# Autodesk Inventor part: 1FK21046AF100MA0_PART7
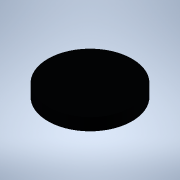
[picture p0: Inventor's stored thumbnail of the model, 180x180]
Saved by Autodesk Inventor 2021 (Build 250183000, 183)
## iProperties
Created: 2025-04
Part Number: 1FK21046AF100MA0_PART7
Material: Generic
Catalog Web Link: www.3dfindit.com
Description: -Servo synchronous motor
Document SubType Name: Modeling
Designer: psAdmin
Mass: 0.299142 g
Surface Area: 3.8585 cm^2
Volume: 0.299142 cm^3
Density: 1 g/cm^3
Appearance: PSOLRGB-38-46-56
Category: PARTsolutions
Title: 1FK21046AF100MA0_PART7
Author: Cadenas PARTsolutions
Comments: Servo synchronous motor
Sending System: PARTsolutions
Preprocessor: ST-DEVELOPER v19.3
PSOL_IDENT_0: {$CADENAS_DATA/23d-libs/siemens_ag/_cat_/4f/2b/1fk21046af100ma0.prj},213 {VTYP=3D},{NB=1FK21046AF100
PSOL_IDENT_1: MA0_PART7},{LINA=1FK21046AF100MA0_PART7},{NN=1FK21046AF100MA0_PART7},{NOPRJ=TRUE},{DATE=19.08.2025 1
PSOL_IDENT_2: 4:00:37},{GEOMDATE=30.07.2025 02:01:06},{VERSION=},{LINEID=10},{WBVAR=},{WBNUMERIC=}  {NB=1FK21046AF
PSOL_IDENT_3: 100MA0_PART7},{LINA=1FK21046AF100MA0_PART7},{KT=DUMMY},{PREVIEW=../../../_pool_/cb/72/p_d211_xx_0043
PSOL_IDENT_4: 4j.png},{DESCSHORT=SIMOTICS S-1FK2 HD, SINAMICS S210 3AC 400V-480V, 3.2 Nm, 3000 rpm},{DESCLONG=SIMO
PSOL_IDENT_5: TICS S-1FK2 HD servo motor M0=3.2 Nm; PN = 1 kW at nN=3000 rpm (380-480 V); PN = 0.5 kW at nN=1500 r
PSOL_IDENT_6: pm (200-240 V); with holding brake; degree of protection IP64; cylindrical shaft D19x40mm; absolute
PSOL_IDENT_7: encoder 22-bit + 12-bit multiturn (encoder AM22DQC); with OCC interface; plug size M17, rotatable; S
PSOL_IDENT_8: IMOTICS S-1FK2 servomotorfor a wide range of uses in industrial environments. SIMOTICS S‑1FK2 servom
PSOL_IDENT_9: otors are compact synchronous motors with a high dynamic performance that set themselves apart as a
PSOL_IDENT_10: result of their high power density, degree of protection and overload capability. The motors are ava
PSOL_IDENT_11: ilable in two variants: as High Dynamic variant (highest dynamic performance as a result of the low
PSOL_IDENT_12: intrinsic moment of inertia for applications demanding a high dynamic performance with low moved mas
PSOL_IDENT_13: ses) - and as Compact variant (precise and stable closed-loop control for medium up to large moved m
PSOL_IDENT_14: asses as a result of a medium intrinsic moment of inertia). SIMOTICSS‑1FK2 servomotors fully exploit
PSOL_IDENT_15: their strengths in a system with the SINAMICSS210 frequency converter and simple connection using t
PSOL_IDENT_16: he one cable connection (OCC). Advantages include the short control and positioning times, fast and
PSOL_IDENT_17: precise correction of disturbing quantities as well as stable control with a high dynamic performanc
PSOL_IDENT_18: e. The servo motors can be configured to address a wide range of requirements. For example with and
PSOL_IDENT_19: without holding brake, IP64 or IP65 degree of protection, singleturn or multiturn absolute encoders
PSOL_IDENT_20: - to name just a few. Further, the servomotors are available in different shaft heights extending fr
PSOL_IDENT_21: om 20 to 100. A shaft sealing ring is available to achieve an IP65 degree of protection and for subs
PSOL_IDENT_22: equent mounting at the motor or as spare part. SIMOTICS - the optimum motor for each and every motio
PSOL_IDENT_23: n control application.},{INTNO=195125049673},{SUPPLIERALTNO=1FK2104-6AF10-0MA0},{MANUID=1FK21046AF10
PSOL_IDENT_24: 0MA0},{MANUNAME=Siemens},{MANUTYPEDESC=Synchronous motor 1FK2-HD 3.2 NM},{AAU732=SIMOTICS},{AAO057=S
PSOL_IDENT_25: -1FK2},{AAU734=SIMOTICS S-1FK2 HD servo motor M0=3.2 Nm; PN = 1 kW at nN=3000 rpm (380-480 V); PN =
PSOL_IDENT_26: 0.5 kW at nN=1500 rpm (200-240 V); with holding brake; degree of protection IP64; cylindrical shaft
PSOL_IDENT_27: D19x40mm; absolute encoder 22-bit + 12-bit multiturn (encoder AM22DQC); with OCC interface; plug siz
PSOL_IDENT_28: e M17, rotatable;},{AAW338=Synchronous motor 1FK2-HD 3.2 NM},{AAO742=SIMOTICS},{AAO663=4042948694534
PSOL_IDENT_29: },{NOCUPEROU=1},{PRICEQUANTITY=1},{QUANTITYMIN=1},{QUANTITYINT=1},{CTN=85015220},{COO=DE},{AAO676=1F
PSOL_IDENT_30: K2104-6AF10-0MA0},{AAO677=Siemens AG},{ORDERUNIT=C62},{CONTENTUNIT=C62}
NB: 1FK21046AF100MA0_PART7
NT: Servo synchronous motor
NBSYN: $MANUID._PART7
LINA: 1FK21046AF100MA0_PART7
CATALOG: SIEMENS
PREVIEW: ../../../_pool_/cb/72/p_d211_xx_00434j.png
DESCSHORT: SIMOTICS S-1FK2 HD, SINAMICS S210 3AC 400V-480V, 3.2 Nm, 3000 rpm
DESCLONG: SIMOTICS S-1FK2 HD servo motor M0=3.2 Nm; PN = 1 kW at nN=3000 rpm (380-480 V); PN = 0.5 kW at nN=1500 rpm (200-240 V); with holding brake; degree of protection
INTNO: 195125049673
SUPPLIERALTNO: 1FK2104-6AF10-0MA0
MANUID: 1FK21046AF100MA0
MANUNAME: Siemens
MANUTYPEDESC: Synchronous motor 1FK2-HD 3.2 NM
AAU732: SIMOTICS
AAO057: S-1FK2
AAU734: SIMOTICS S-1FK2 HD servo motor M0=3.2 Nm; PN = 1 kW at nN=3000 rpm (380-480 V); PN = 0.5 kW at nN=1500 rpm (200-240 V); with holding brake; degree of protection
AAW338: Synchronous motor 1FK2-HD 3.2 NM
AAO742: SIMOTICS
AAO663: 4042948694534.0
NOCUPEROU: 1
PRICEQUANTITY: 1
QUANTITYMIN: 1
QUANTITYINT: 1
CTN: 85015220
COO: DE
ARTICLENO: 1FK21046AF100MA0_PART7
BOMINFO: 1FK21046AF100MA0_PART7
CREATOR: CADENAS GmbH
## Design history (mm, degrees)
feature "2025_04_17_14_59_39_0146"
body "Solid1"
